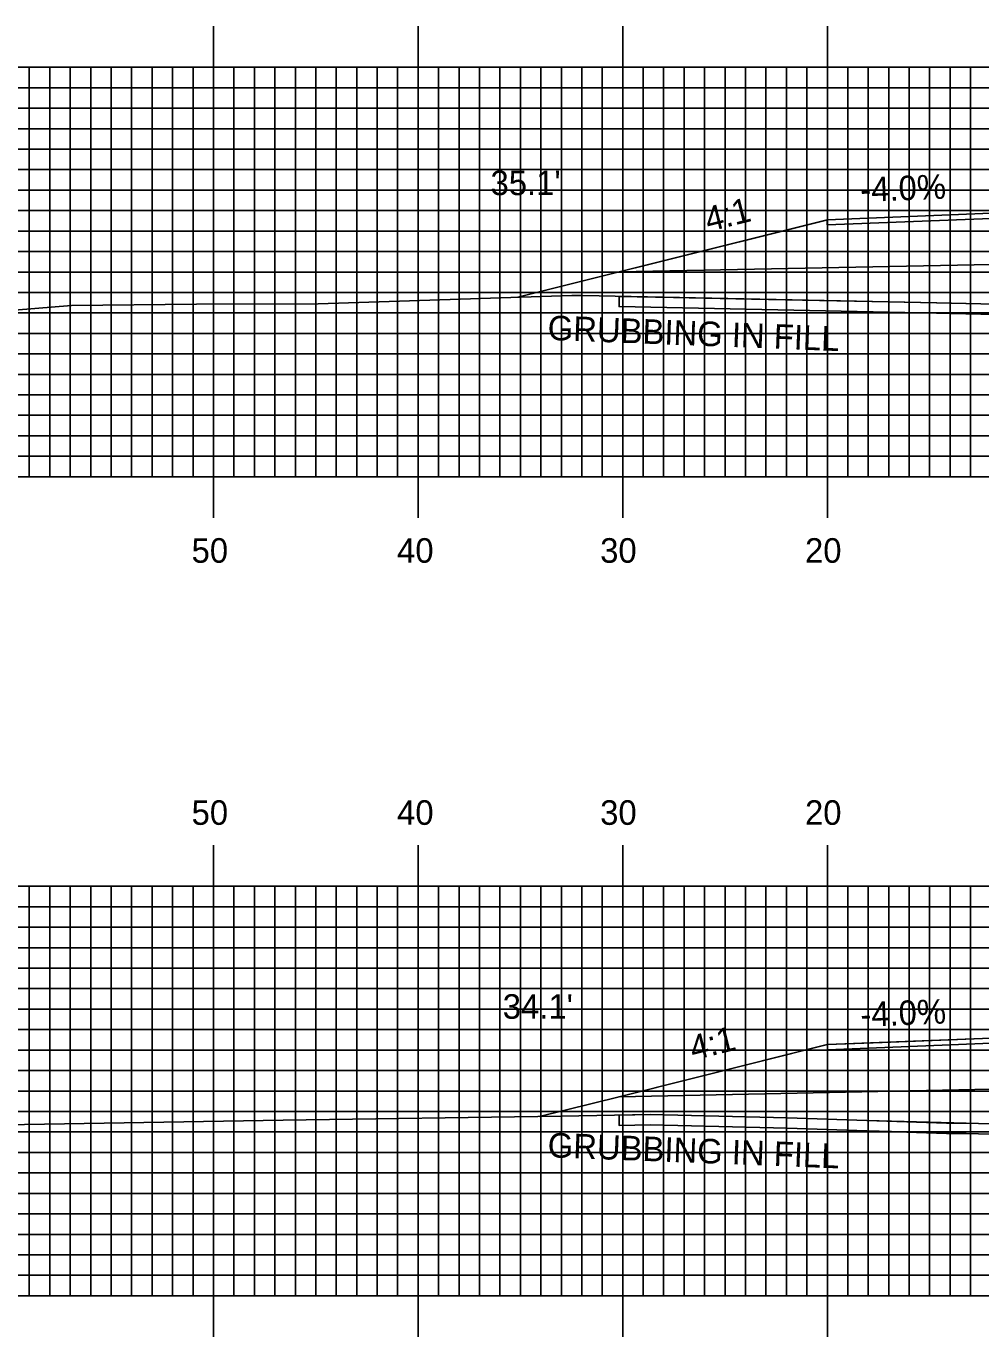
# Model space of a CAD drawing. Extents: x 1763759 to 1764102, y 442591 to 442811.
# Drawn here: x 1763865.2 to 1763911.8, y 442696.7 to 442760.7 of the extents above; entities that cross this region are included whole.
import ezdxf

# ---------------------------------------------------------------- set-up
doc = ezdxf.new("R2010")
doc.units = 0
for name, color, linetype in [('ANNOTATION', 7, 'Continuous'), ('D_Roadway_Centerline', 7, 'Continuous'), ('D_Roadway_Edge_Shoulder', 7, 'Continuous'), ('D_Roadway_SlopeLines', 7, 'Continuous'), ('D_Roadway_SubGrade', 7, 'Continuous'), ('D_Text_Standard', 7, 'Continuous'), ('GRUBBING IN FILL', 7, 'Continuous'), ('H_V ANNOTATION', 7, 'Continuous'), ('MAJOR', 7, 'Continuous'), ('MINOR', 7, 'Continuous'), ('S_Roadway_Centerline', 7, 'Continuous')]:
    doc.layers.add(name, color=color, linetype=linetype)

msp = doc.modelspace()

# ---------------------------------------------------------------- linework, layer by layer
at = {"layer": 'D_Roadway_Centerline'}
for points in [[(1763889.187, 442747.431), (1763889.189, 442747.432), (1763890.566, 442747.776), (1763894.144, 442748.67), (1763895.666, 442749.05), (1763904.277, 442751.203), (1763904.318, 442751.213), (1763912.318, 442751.533), (1763924.315, 442751.773), (1763924.319, 442751.773), (1763936.313, 442751.533), (1763936.319, 442751.533), (1763937.226, 442751.497), (1763944.314, 442751.213), (1763944.319, 442751.213), (1763951.794, 442749.345), (1763954.48, 442748.673), (1763954.493, 442748.67), (1763954.495, 442748.67), (1763954.995, 442748.544), (1763956.319, 442748.213), (1763961.352, 442746.955), (1763962.976, 442746.549)], [(1763890.259, 442707.415), (1763894.144, 442708.386), (1763897.914, 442709.329), (1763904.312, 442710.929), (1763904.319, 442710.93), (1763904.324, 442710.93), (1763907.002, 442711.038), (1763912.316, 442711.25), (1763912.319, 442711.25), (1763923.434, 442711.473), (1763924.318, 442711.49), (1763936.316, 442711.25), (1763936.318, 442711.25), (1763944.308, 442710.931), (1763944.319, 442710.93), (1763954.486, 442708.388), (1763954.492, 442708.386), (1763956.316, 442707.931), (1763956.319, 442707.93), (1763961.907, 442706.533), (1763961.911, 442706.532)]]:
    msp.add_lwpolyline(points, dxfattribs=at)
at = {"layer": 'D_Roadway_Edge_Shoulder'}
for points in [[(1763912.318, 442751.533), (1763904.318, 442751.213), (1763904.318, 442750.963), (1763912.318, 442751.283)], [(1763912.319, 442711.25), (1763904.319, 442710.93), (1763904.319, 442710.68), (1763912.319, 442711)]]:
    msp.add_lwpolyline(points, close=True, dxfattribs=at)
at = {"layer": 'D_Roadway_SlopeLines'}
msp.add_lwpolyline([(1763904.318, 442751.213), (1763894.144, 442748.67), (1763889.187, 442747.431)], dxfattribs=at)
at = {"layer": 'D_Roadway_SubGrade'}
for points in [[(1763904.318, 442750.963), (1763912.318, 442751.283), (1763912.318, 442750.867), (1763912.318, 442749.033), (1763894.144, 442748.67), (1763904.318, 442751.213)], [(1763904.319, 442710.68), (1763912.319, 442711), (1763912.319, 442710.583), (1763912.319, 442708.75), (1763894.144, 442708.386), (1763904.319, 442710.93)]]:
    msp.add_lwpolyline(points, close=True, dxfattribs=at)
at = {"layer": 'GRUBBING IN FILL'}
for p, q in [((1763894.144, 442747.474), (1763894.144, 442746.974)), ((1763894.144, 442707.484), (1763894.144, 442706.984))]:
    msp.add_line(p, q, dxfattribs=at)
for points in [[(1763894.144, 442747.474), (1763896.804, 442747.419), (1763900.618, 442747.34), (1763903.942, 442747.272), (1763906.489, 442747.219), (1763909.661, 442747.153), (1763913.259, 442747.074), (1763916.85, 442746.996), (1763919.345, 442747.064), (1763922.156, 442747.141), (1763924.319, 442747.201), (1763924.319, 442746.7), (1763922.255, 442746.644), (1763916.851, 442746.496), (1763909.658, 442746.653), (1763901.901, 442746.814), (1763894.144, 442746.974)], [(1763894.144, 442747.474), (1763896.804, 442747.419), (1763900.618, 442747.34), (1763903.942, 442747.272), (1763906.489, 442747.219), (1763909.661, 442747.153), (1763913.259, 442747.074), (1763916.85, 442746.996), (1763919.345, 442747.064), (1763922.156, 442747.141), (1763924.319, 442747.201), (1763924.319, 442746.7), (1763922.255, 442746.644), (1763916.851, 442746.496), (1763909.658, 442746.653), (1763901.901, 442746.814), (1763894.144, 442746.974)], [(1763894.144, 442707.484), (1763895.682, 442707.514), (1763899.02, 442707.435), (1763902.359, 442707.356), (1763906.253, 442707.223), (1763911.7, 442707.075), (1763913.254, 442707.06), (1763917.035, 442707.049), (1763920.815, 442707.039), (1763924.319, 442707.036), (1763924.319, 442706.536), (1763920.815, 442706.539), (1763917.035, 442706.549), (1763911.7, 442706.575), (1763906.253, 442706.723), (1763902.359, 442706.856), (1763899.02, 442706.935), (1763895.682, 442707.014), (1763894.144, 442706.984)], [(1763894.144, 442707.484), (1763895.682, 442707.514), (1763899.02, 442707.435), (1763902.359, 442707.356), (1763906.253, 442707.223), (1763911.7, 442707.075), (1763913.254, 442707.06), (1763917.035, 442707.049), (1763920.815, 442707.039), (1763924.319, 442707.036), (1763924.319, 442706.536), (1763920.815, 442706.539), (1763917.035, 442706.549), (1763911.7, 442706.575), (1763906.253, 442706.723), (1763902.359, 442706.856), (1763899.02, 442706.935), (1763895.682, 442707.014), (1763894.144, 442706.984)]]:
    msp.add_lwpolyline(points, close=True, dxfattribs=at)
for points in [[(1763894.144, 442746.974), (1763909.658, 442746.653), (1763916.851, 442746.496), (1763927.658, 442746.792), (1763928.936, 442746.807), (1763932.205, 442746.591), (1763935.455, 442746.595), (1763943.397, 442746.68), (1763943.442, 442746.68), (1763951.678, 442746.514), (1763954.493, 442746.398)], [(1763894.144, 442706.984), (1763895.682, 442707.014), (1763902.359, 442706.856), (1763910.147, 442706.59), (1763913.254, 442706.56), (1763920.815, 442706.539), (1763931.106, 442706.532), (1763934.963, 442706.532), (1763942.948, 442706.398), (1763947.209, 442706.321), (1763949.3, 442706.288), (1763952.904, 442706.144), (1763954.492, 442706.145)]]:
    msp.add_lwpolyline(points, dxfattribs=at)
at = {"layer": 'MAJOR'}
for p, q in [((1763874.319, 442760.669), (1763874.319, 442758.665)), ((1763884.319, 442760.669), (1763884.319, 442758.665)), ((1763894.319, 442760.669), (1763894.319, 442758.665)), ((1763904.319, 442760.669), (1763904.319, 442758.665)), ((1763784.319, 442758.665), (1764064.319, 442758.665)), ((1763784.319, 442758.665), (1764064.319, 442758.665)), ((1763874.319, 442738.665), (1763874.319, 442758.665)), ((1763884.319, 442738.665), (1763884.319, 442758.665)), ((1763894.319, 442738.665), (1763894.319, 442758.665)), ((1763904.319, 442738.665), (1763904.319, 442758.665)), ((1763784.319, 442753.665), (1764064.319, 442753.665)), ((1763784.319, 442748.665), (1764064.319, 442748.665)), ((1763784.319, 442743.665), (1764064.319, 442743.665)), ((1763784.319, 442738.665), (1764064.319, 442738.665)), ((1763784.319, 442738.665), (1764064.319, 442738.665)), ((1763874.319, 442736.661), (1763874.319, 442738.665)), ((1763884.319, 442736.661), (1763884.319, 442738.665)), ((1763894.319, 442736.661), (1763894.319, 442738.665)), ((1763904.319, 442736.661), (1763904.319, 442738.665)), ((1763874.319, 442720.669), (1763874.319, 442718.665)), ((1763884.319, 442720.669), (1763884.319, 442718.665)), ((1763894.319, 442720.669), (1763894.319, 442718.665)), ((1763904.319, 442720.669), (1763904.319, 442718.665)), ((1763784.319, 442718.665), (1764064.319, 442718.665)), ((1763784.319, 442718.665), (1764064.319, 442718.665)), ((1763874.319, 442698.665), (1763874.319, 442718.665)), ((1763884.319, 442698.665), (1763884.319, 442718.665)), ((1763894.319, 442698.665), (1763894.319, 442718.665)), ((1763904.319, 442698.665), (1763904.319, 442718.665)), ((1763784.319, 442713.665), (1764064.319, 442713.665)), ((1763784.319, 442708.665), (1764064.319, 442708.665)), ((1763784.319, 442703.665), (1764064.319, 442703.665)), ((1763784.319, 442698.665), (1764064.319, 442698.665)), ((1763784.319, 442698.665), (1764064.319, 442698.665)), ((1763874.319, 442696.661), (1763874.319, 442698.665)), ((1763884.319, 442696.661), (1763884.319, 442698.665)), ((1763894.319, 442696.661), (1763894.319, 442698.665)), ((1763904.319, 442696.661), (1763904.319, 442698.665))]:
    msp.add_line(p, q, dxfattribs=at)
at = {"layer": 'MINOR'}
for p, q in [((1763865.319, 442738.665), (1763865.319, 442758.665)), ((1763866.319, 442738.665), (1763866.319, 442758.665)), ((1763867.319, 442738.665), (1763867.319, 442758.665)), ((1763868.319, 442738.665), (1763868.319, 442758.665)), ((1763869.319, 442738.665), (1763869.319, 442758.665)), ((1763870.319, 442738.665), (1763870.319, 442758.665)), ((1763871.319, 442738.665), (1763871.319, 442758.665)), ((1763872.319, 442738.665), (1763872.319, 442758.665)), ((1763873.319, 442738.665), (1763873.319, 442758.665)), ((1763875.319, 442738.665), (1763875.319, 442758.665)), ((1763876.319, 442738.665), (1763876.319, 442758.665)), ((1763877.319, 442738.665), (1763877.319, 442758.665)), ((1763878.319, 442738.665), (1763878.319, 442758.665)), ((1763879.319, 442738.665), (1763879.319, 442758.665)), ((1763880.319, 442738.665), (1763880.319, 442758.665)), ((1763881.319, 442738.665), (1763881.319, 442758.665)), ((1763882.319, 442738.665), (1763882.319, 442758.665)), ((1763883.319, 442738.665), (1763883.319, 442758.665)), ((1763885.319, 442738.665), (1763885.319, 442758.665)), ((1763886.319, 442738.665), (1763886.319, 442758.665)), ((1763887.319, 442738.665), (1763887.319, 442758.665)), ((1763888.319, 442738.665), (1763888.319, 442758.665)), ((1763889.319, 442738.665), (1763889.319, 442758.665)), ((1763890.319, 442738.665), (1763890.319, 442758.665)), ((1763891.319, 442738.665), (1763891.319, 442758.665)), ((1763892.319, 442738.665), (1763892.319, 442758.665)), ((1763893.319, 442738.665), (1763893.319, 442758.665)), ((1763895.319, 442738.665), (1763895.319, 442758.665)), ((1763896.319, 442738.665), (1763896.319, 442758.665)), ((1763897.319, 442738.665), (1763897.319, 442758.665)), ((1763898.319, 442738.665), (1763898.319, 442758.665)), ((1763899.319, 442738.665), (1763899.319, 442758.665)), ((1763900.319, 442738.665), (1763900.319, 442758.665)), ((1763901.319, 442738.665), (1763901.319, 442758.665)), ((1763902.319, 442738.665), (1763902.319, 442758.665)), ((1763903.319, 442738.665), (1763903.319, 442758.665)), ((1763905.319, 442738.665), (1763905.319, 442758.665)), ((1763906.319, 442738.665), (1763906.319, 442758.665)), ((1763907.319, 442738.665), (1763907.319, 442758.665)), ((1763908.319, 442738.665), (1763908.319, 442758.665)), ((1763909.319, 442738.665), (1763909.319, 442758.665)), ((1763910.319, 442738.665), (1763910.319, 442758.665)), ((1763911.319, 442738.665), (1763911.319, 442758.665)), ((1763784.319, 442757.665), (1764064.319, 442757.665)), ((1763784.319, 442756.665), (1764064.319, 442756.665)), ((1763784.319, 442755.665), (1764064.319, 442755.665)), ((1763784.319, 442754.665), (1764064.319, 442754.665)), ((1763784.319, 442752.665), (1764064.319, 442752.665)), ((1763784.319, 442751.665), (1764064.319, 442751.665)), ((1763784.319, 442750.665), (1764064.319, 442750.665)), ((1763784.319, 442749.665), (1764064.319, 442749.665)), ((1763784.319, 442747.665), (1764064.319, 442747.665)), ((1763784.319, 442746.665), (1764064.319, 442746.665)), ((1763784.319, 442745.665), (1764064.319, 442745.665)), ((1763784.319, 442744.665), (1764064.319, 442744.665)), ((1763784.319, 442742.665), (1764064.319, 442742.665)), ((1763784.319, 442741.665), (1764064.319, 442741.665)), ((1763784.319, 442740.665), (1764064.319, 442740.665)), ((1763784.319, 442739.665), (1764064.319, 442739.665)), ((1763865.319, 442698.665), (1763865.319, 442718.665)), ((1763866.319, 442698.665), (1763866.319, 442718.665)), ((1763867.319, 442698.665), (1763867.319, 442718.665)), ((1763868.319, 442698.665), (1763868.319, 442718.665)), ((1763869.319, 442698.665), (1763869.319, 442718.665)), ((1763870.319, 442698.665), (1763870.319, 442718.665)), ((1763871.319, 442698.665), (1763871.319, 442718.665)), ((1763872.319, 442698.665), (1763872.319, 442718.665)), ((1763873.319, 442698.665), (1763873.319, 442718.665)), ((1763875.319, 442698.665), (1763875.319, 442718.665)), ((1763876.319, 442698.665), (1763876.319, 442718.665)), ((1763877.319, 442698.665), (1763877.319, 442718.665)), ((1763878.319, 442698.665), (1763878.319, 442718.665)), ((1763879.319, 442698.665), (1763879.319, 442718.665)), ((1763880.319, 442698.665), (1763880.319, 442718.665)), ((1763881.319, 442698.665), (1763881.319, 442718.665)), ((1763882.319, 442698.665), (1763882.319, 442718.665)), ((1763883.319, 442698.665), (1763883.319, 442718.665)), ((1763885.319, 442698.665), (1763885.319, 442718.665)), ((1763886.319, 442698.665), (1763886.319, 442718.665)), ((1763887.319, 442698.665), (1763887.319, 442718.665)), ((1763888.319, 442698.665), (1763888.319, 442718.665)), ((1763889.319, 442698.665), (1763889.319, 442718.665)), ((1763890.319, 442698.665), (1763890.319, 442718.665)), ((1763891.319, 442698.665), (1763891.319, 442718.665)), ((1763892.319, 442698.665), (1763892.319, 442718.665)), ((1763893.319, 442698.665), (1763893.319, 442718.665)), ((1763895.319, 442698.665), (1763895.319, 442718.665)), ((1763896.319, 442698.665), (1763896.319, 442718.665)), ((1763897.319, 442698.665), (1763897.319, 442718.665)), ((1763898.319, 442698.665), (1763898.319, 442718.665)), ((1763899.319, 442698.665), (1763899.319, 442718.665)), ((1763900.319, 442698.665), (1763900.319, 442718.665)), ((1763901.319, 442698.665), (1763901.319, 442718.665)), ((1763902.319, 442698.665), (1763902.319, 442718.665)), ((1763903.319, 442698.665), (1763903.319, 442718.665)), ((1763905.319, 442698.665), (1763905.319, 442718.665)), ((1763906.319, 442698.665), (1763906.319, 442718.665)), ((1763907.319, 442698.665), (1763907.319, 442718.665)), ((1763908.319, 442698.665), (1763908.319, 442718.665)), ((1763909.319, 442698.665), (1763909.319, 442718.665)), ((1763910.319, 442698.665), (1763910.319, 442718.665)), ((1763911.319, 442698.665), (1763911.319, 442718.665)), ((1763784.319, 442717.665), (1764064.319, 442717.665)), ((1763784.319, 442716.665), (1764064.319, 442716.665)), ((1763784.319, 442715.665), (1764064.319, 442715.665)), ((1763784.319, 442714.665), (1764064.319, 442714.665)), ((1763784.319, 442712.665), (1764064.319, 442712.665)), ((1763784.319, 442711.665), (1764064.319, 442711.665)), ((1763784.319, 442710.665), (1764064.319, 442710.665)), ((1763784.319, 442709.665), (1764064.319, 442709.665)), ((1763784.319, 442707.665), (1764064.319, 442707.665)), ((1763784.319, 442706.665), (1764064.319, 442706.665)), ((1763784.319, 442705.665), (1764064.319, 442705.665)), ((1763784.319, 442704.665), (1764064.319, 442704.665)), ((1763784.319, 442702.665), (1764064.319, 442702.665)), ((1763784.319, 442701.665), (1764064.319, 442701.665)), ((1763784.319, 442700.665), (1764064.319, 442700.665)), ((1763784.319, 442699.665), (1764064.319, 442699.665))]:
    msp.add_line(p, q, dxfattribs=at)
at = {"layer": 'S_Roadway_Centerline'}
for points in [[(1763854.828, 442746.006), (1763867.386, 442747.029), (1763873.489, 442747.092), (1763879.439, 442747.107), (1763891.836, 442747.519), (1763892.337, 442747.514), (1763893.166, 442747.494), (1763909.668, 442747.153), (1763916.85, 442746.996), (1763927.648, 442747.292), (1763928.95, 442747.308), (1763932.221, 442747.091), (1763935.452, 442747.095), (1763943.395, 442747.18), (1763943.448, 442747.18), (1763951.694, 442747.014), (1763963.571, 442746.525), (1763967.273, 442746.276), (1763975.063, 442745.732)], [(1763860.214, 442706.945), (1763877.726, 442707.246), (1763891.289, 442707.429), (1763895.682, 442707.514), (1763902.359, 442707.356), (1763910.147, 442707.09), (1763913.254, 442707.06), (1763920.815, 442707.039), (1763931.106, 442707.032), (1763934.963, 442707.032), (1763942.948, 442706.898), (1763947.209, 442706.821), (1763949.3, 442706.788), (1763952.904, 442706.644), (1763955.503, 442706.646), (1763961.357, 442706.549), (1763966.71, 442706.383), (1763966.789, 442706.364), (1763983.488, 442705.893)]]:
    msp.add_lwpolyline(points, dxfattribs=at)

# ---------------------------------------------------------------- texts
at = {"layer": 'ANNOTATION'}
for s, rotation, p in [('-4.0%', 2.29064, (1763905.95, 442752.08)), ('4:1', 14.03364, (1763898.507, 442750.622)), ('-4.0%', 2.29063, (1763905.952, 442711.797)), ('4:1', 14.0377, (1763897.764, 442710.153))]:
    msp.add_text(s, height=1.2, rotation=rotation, dxfattribs=at).set_placement(p)
at = {"layer": 'D_Text_Standard'}
for s, p in [("35.1'", (1763887.857, 442752.418)), ("34.1'", (1763888.454, 442712.193))]:
    msp.add_text(s, height=1.2, dxfattribs=at).set_placement(p)
at = {"layer": 'GRUBBING IN FILL'}
for p in [(1763890.633, 442745.349), (1763890.633, 442705.433)]:
    msp.add_text('GRUBBING IN FILL', height=1.2, rotation=357.79811, dxfattribs=at).set_placement(p)
at = {"layer": 'H_V ANNOTATION'}
for s, p in [('50', (1763873.248, 442734.465)), ('40', (1763883.291, 442734.465)), ('30', (1763893.216, 442734.465)), ('20', (1763903.227, 442734.465)), ('50', (1763873.248, 442721.665)), ('40', (1763883.291, 442721.665)), ('30', (1763893.216, 442721.665)), ('20', (1763903.227, 442721.665))]:
    msp.add_text(s, height=1.2, dxfattribs=at).set_placement(p)

doc.saveas('drawing.dxf')
